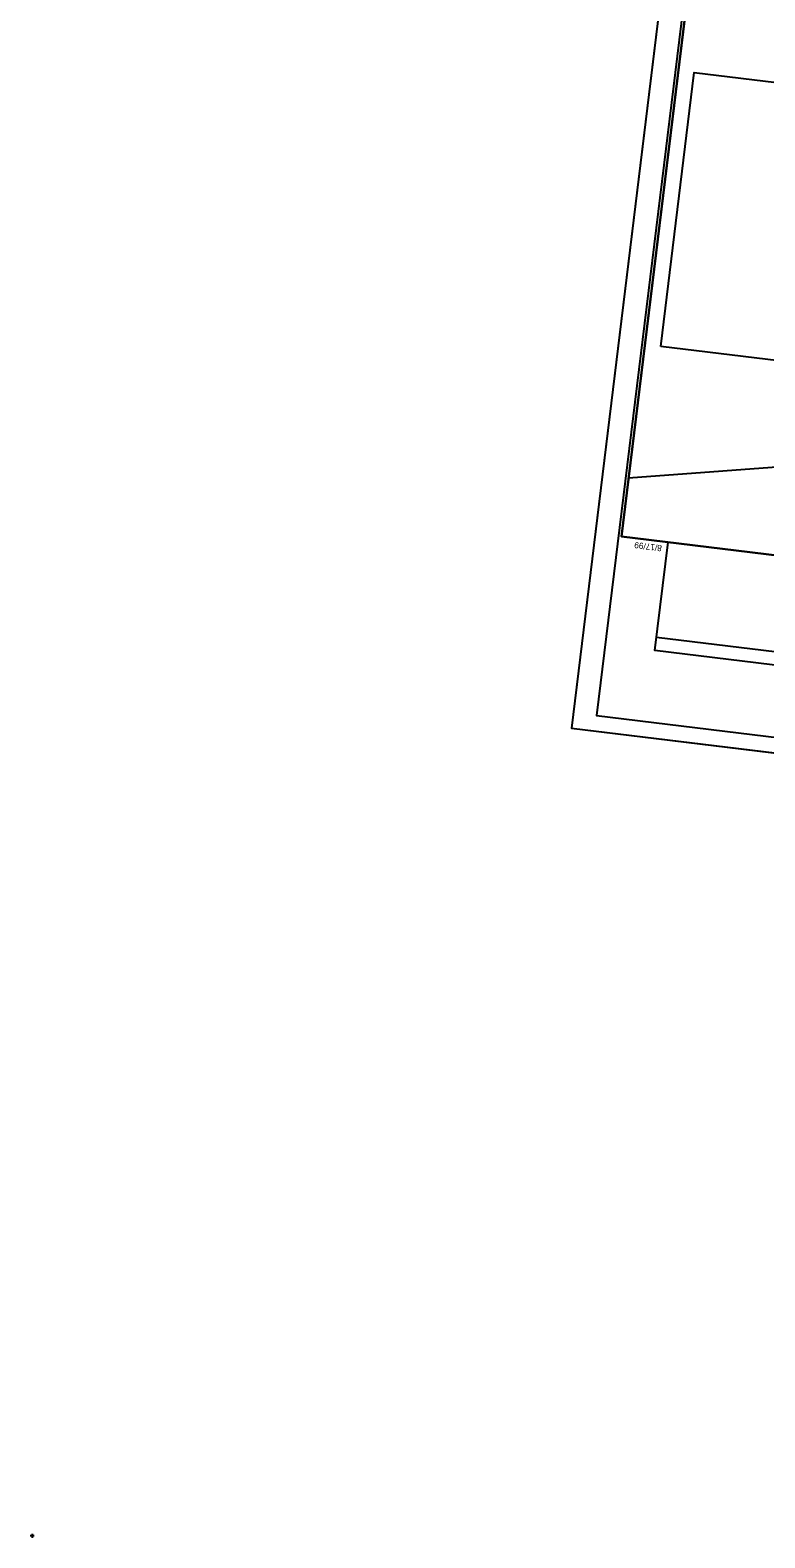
# Model space of a CAD drawing. Extents: x 480344 to 482186, y 489602 to 491961.
# Drawn here: x 480344 to 480967, y 489602 to 490882 of the extents above; entities that cross this region are included whole.
import ezdxf

# ---------------------------------------------------------------- set-up
doc = ezdxf.new("R2010")
doc.units = 0
for name, color, linetype in [('Old_Level_1', 7, 'Continuous'), ('Sheet Block Revision CELL', 7, 'Continuous'), ('Sheet Clip Boundary CELL', 7, 'Continuous'), ('Sheet Cutting Line CELL', 7, 'Continuous'), ('Sheet Layout Plan Border', 7, 'Continuous'), ('Sheet Plan CELL', 7, 'Continuous'), ('Sheet Plot Border Inside CELL', 7, 'Continuous'), ('Sheet Plot Border Outside CELL', 7, 'Continuous')]:
    doc.layers.add(name, color=color, linetype=linetype)

msp = doc.modelspace()

# ---------------------------------------------------------------- linework, layer by layer
at = {"layer": 'Old_Level_1'}
for p, q in [((480347.5, 489603.9), (480344, 489603.9)), ((480345.8, 489605.7), (480345.8, 489602.2))]:
    msp.add_line(p, q, dxfattribs=at)
at = {"layer": 'Sheet Block Revision CELL'}
msp.add_line((481660.4, 490270.4), (480875.6, 490366.3), dxfattribs=at)
msp.add_lwpolyline([(481659, 490259.3), (480874.2, 490355.2), (480885.4, 490447.2), (481670.2, 490351.4)], close=True, dxfattribs=at)
at = {"layer": 'Sheet Clip Boundary CELL'}
msp.add_lwpolyline([(480879.2, 490613.3), (480907.6, 490845.7), (481017, 490832.4), (480988.6, 490599.9)], close=True, dxfattribs=at)
at = {"layer": 'Sheet Cutting Line CELL'}
for p, q in [((481007.4, 491960.6), (480803.3, 490289.5)), ((480803.3, 490289.5), (481890.2, 490156.8))]:
    msp.add_line(p, q, dxfattribs=at)
at = {"layer": 'Sheet Layout Plan Border'}
for points in [[(481091.9, 490519.7), (481587.5, 490459.2), (481698.3, 490347.9), (481789.2, 490336.8), (481888, 490324.8), (481894.1, 490374.4), (482045.3, 491612.4), (481950.4, 491623.3), (481975.4, 491825.3), (481441.9, 491890.4), (481190.7, 491844.8), (481175.6, 491721.4), (481003.4, 491742.5), (480851.8, 490501.7)], [(481091.9, 490519.7), (481587.5, 490459.2), (481698.3, 490347.9), (481789.2, 490336.8), (481888, 490324.8), (481894.1, 490374.4), (482045.3, 491612.4), (481950.4, 491623.3), (481955.4, 491662), (481633.7, 491701.3), (481441.9, 491890.4), (481190.7, 491844.8), (481175.6, 491721.4), (481003.4, 491742.5), (480851.8, 490501.7)]]:
    msp.add_lwpolyline(points, close=True, dxfattribs=at)
at = {"layer": 'Sheet Plan CELL'}
msp.add_line((480845.8, 490452.1), (480845.8, 490452.1), dxfattribs=at)
for points in [[(481027.6, 491941), (480845.8, 490452.1), (481888, 490324.8), (482069.9, 491813.7)], [(481888, 490324.8), (480845.8, 490452), (481003.4, 491742.4), (481152.3, 491724.3), (481176.6, 491922.8), (482069.9, 491813.7)]]:
    msp.add_lwpolyline(points, close=True, dxfattribs=at)
at = {"layer": 'Sheet Plot Border Inside CELL'}
msp.add_lwpolyline([(481871.9, 490172.1), (482073.9, 491825.8), (481026.7, 491953.7), (480824.7, 490300)], close=True, dxfattribs=at)
at = {"layer": 'Sheet Plot Border Outside CELL'}
msp.add_lwpolyline([(481890.2, 490156.8), (482094.3, 491827.9), (481007.4, 491960.6), (480803.3, 490289.5)], close=True, dxfattribs=at)

# ---------------------------------------------------------------- texts
at = {"layer": 'Sheet Plan CELL'}
msp.add_text('8/17/99', height=5.25, rotation=173.0365, dxfattribs=at).set_placement((480880.3, 490444.6))

doc.saveas('drawing.dxf')
